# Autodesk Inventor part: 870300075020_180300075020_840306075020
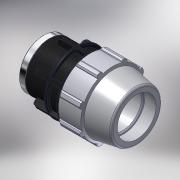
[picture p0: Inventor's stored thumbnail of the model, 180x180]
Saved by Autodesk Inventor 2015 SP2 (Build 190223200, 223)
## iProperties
Created: 2017-02
Part Number: 870300075020_180300075020_840306075020
Material: PVC-Piping
Description: PLASSON FEMALE ADAPTOR 75-2"
Document SubType Name: Modeling
Designer: KIM
Mass: 92.6774 g
Surface Area: 199.44 cm^2
Volume: 66.1981 cm^3
Density: 1.4 g/cm^3
Appearance: PTFE
Author: KIM
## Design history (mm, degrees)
derived "87030.ipt"
feature "Solid1::87030.ipt"
tag "TaggingFeature1"
body "Solid1"
other parameters: "d2" = 75, "d4" = 25.85714, "d5" = 45.25, "d7" = 132, "d9" = 25.85714, "d11" = 5.17143, "d12" = 105.6, "d13" = 120 deg, "d14" = 97.5, "d15" = 10 deg, "d16" = 118.8, "d18" = 3.75, "d19" = 35 deg, "d20" = 17.5 deg, "d21" = 122.76, "d23" = 0, "d25" = 360 deg, "d27" = 2.64, "d34" = 6.6, "d35" = 54.3, "d36" = 0, "d42" = 45.25, "d43" = 3.96, "d46" = 2.25, "d49" = 137, "d51" = 181, "d53" = 1.5, "d55" = 360 deg, "d62" = 48.75, "d63" = 56.656, "d64" = 60.33333, "d65" = 6.6, "d69" = 95.04, "d70" = 3.3, "d71" = 12.6, "d72" = 0.5, "d73" = 1, "d_" = 75, "E_" = 132, "H_" = 181, "l_" = 137, "Rp_Rc_" = 56.656
